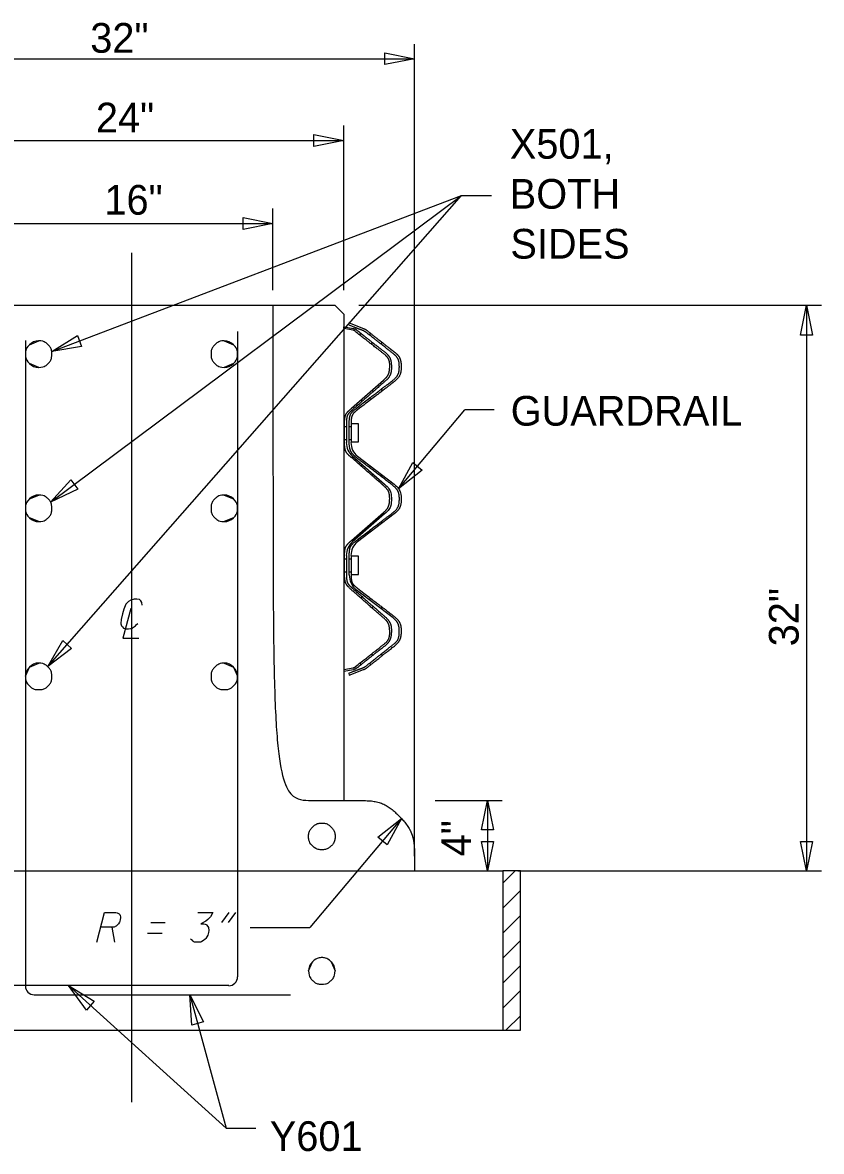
# Model space of a CAD drawing. Extents: x 0 to 680, y 0 to 440.
# Drawn here: x 76.9 to 152, y 200.4 to 306.5 of the extents above; entities that cross this region are included whole.
import ezdxf

# ---------------------------------------------------------------- set-up
doc = ezdxf.new("R2010")
doc.units = 0
doc.layers.add('Default', color=7, linetype='Continuous')

msp = doc.modelspace()

# ---------------------------------------------------------------- linework, layer by layer
at = {"layer": 'Default'}
for p, q in [((113.77, 228.1), (113.77, 304.44)), ((60.56, 303.06), (113.77, 303.06)), ((107.12, 281.31), (107.12, 296.77)), ((79.3, 245.92), (118.2, 290.2)), ((79.54, 261.38), (118.2, 290.2)), ((79.68, 275.54), (118.2, 290.2)), ((118.2, 290.2), (121, 290.2)), ((100.47, 281.31), (100.47, 288.98)), ((87.16, 284.82), (87.16, 204.99)), ((108.53, 279.89), (152.03, 279.89)), ((150.62, 279.89), (150.62, 226.72)), ((107.59, 278.04), (107.64, 278.23)), ((107.64, 278.23), (108.97, 277.7)), ((97.14, 277.43), (97.14, 216.77)), ((107.14, 277.87), (108.03, 277.7)), ((107.14, 277.7), (107.14, 277.87)), ((108, 277.54), (107.14, 277.7)), ((108.64, 277.09), (108.72, 277.23)), ((109.55, 277.09), (109.64, 277.23)), ((77.19, 276.57), (77.19, 215.91)), ((77.58, 276.18), (78.44, 276.54)), ((95.89, 276.54), (96.75, 276.18)), ((109.72, 276.23), (109.83, 276.4)), ((110.64, 276.23), (110.72, 276.4)), ((78.44, 274.05), (77.58, 274.41)), ((96.75, 274.41), (95.89, 274.05)), ((107.86, 270.22), (110.86, 272.85)), ((109.8, 271.91), (109.89, 271.75)), ((110.64, 272), (110.75, 271.83)), ((108.75, 270.97), (108.83, 270.83)), ((109.55, 271.16), (109.64, 271)), ((112.27, 262.63), (118.5, 270.06)), ((121.28, 270.06), (118.5, 270.06)), ((107.2, 266.98), (107.2, 268.81)), ((107.2, 268.5), (107.37, 268.5)), ((107.37, 268.81), (107.37, 266.98)), ((107.64, 266.98), (107.64, 268.81)), ((107.64, 268.5), (107.81, 268.5)), ((107.81, 268.81), (107.81, 266.98)), ((107.2, 267.28), (107.37, 267.28)), ((107.64, 267.28), (107.81, 267.28)), ((107.92, 265.73), (110.94, 263.07)), ((108.42, 265.7), (111.85, 263.07)), ((108.75, 264.79), (108.83, 264.93)), ((109.55, 264.62), (109.64, 264.76)), ((109.8, 263.88), (109.89, 264.01)), ((110.64, 263.77), (110.75, 263.93)), ((77.58, 261.69), (78.44, 262.05)), ((95.89, 262.05), (96.75, 261.69)), ((107.86, 257.78), (110.86, 260.41)), ((110.94, 260.27), (107.95, 257.64)), ((111.85, 260.27), (108.42, 257.64)), ((78.44, 259.55), (77.58, 259.91)), ((96.75, 259.91), (95.89, 259.55)), ((109.8, 259.47), (109.89, 259.33)), ((110.64, 259.58), (110.75, 259.41)), ((108.75, 258.56), (108.83, 258.39)), ((109.55, 258.72), (109.64, 258.58)), ((107.2, 256.06), (107.37, 256.06)), ((107.37, 256.37), (107.37, 254.54)), ((107.64, 254.54), (107.64, 256.37)), ((107.64, 256.06), (107.81, 256.06)), ((107.81, 256.37), (107.81, 254.54)), ((107.2, 254.84), (107.37, 254.84)), ((107.64, 254.84), (107.81, 254.84)), ((111.77, 250.52), (108.31, 253.12)), ((108.75, 252.38), (108.83, 252.52)), ((109.55, 252.18), (109.64, 252.35)), ((109.8, 251.43), (109.89, 251.6)), ((110.64, 251.35), (110.75, 251.52)), ((77.58, 245.86), (78.44, 246.25)), ((95.89, 246.25), (96.75, 245.86)), ((108.64, 246.25), (108.72, 246.11)), ((109.55, 246.25), (109.64, 246.11)), ((109.72, 247.11), (109.83, 246.97)), ((110.64, 247.11), (110.72, 246.97)), ((77.19, 245.01), (77.58, 245.86)), ((96.75, 245.86), (97.14, 245.01)), ((107.14, 245.64), (108, 245.81)), ((107.59, 245.31), (107.64, 245.12)), ((107.64, 245.12), (108.97, 245.64)), ((115.71, 233.34), (122.02, 233.34)), ((120.64, 233.34), (120.64, 226.72)), ((112.55, 231.65), (103.93, 221.4)), ((115.18, 226.72), (122.02, 226.72)), ((123.2, 226.7), (122.08, 225.56)), ((123.49, 226.72), (152.03, 226.72)), ((123.74, 224.89), (122.08, 223.23)), ((96.31, 222.81), (95.62, 221.87)), ((96.95, 222.81), (96.25, 221.87)), ((88.97, 221.87), (90.32, 221.87)), ((123.74, 222.53), (122.08, 220.87)), ((85.31, 221.42), (85.56, 220.01)), ((88.66, 220.87), (90.05, 220.87)), ((98.33, 221.4), (103.93, 221.4)), ((123.74, 220.18), (122.08, 218.52)), ((103.82, 217.32), (104.18, 218.18)), ((105.95, 218.18), (106.31, 217.32)), ((123.74, 217.82), (122.08, 216.16)), ((96.31, 215.94), (72.2, 215.94)), ((81.24, 215.94), (96.06, 202.53)), ((123.74, 215.47), (122.08, 213.81)), ((78.02, 215.08), (102.13, 215.08)), ((92.65, 215.08), (96.06, 202.53)), ((122.36, 211.75), (123.74, 213.11)), ((52.28, 211.75), (122.08, 211.75)), ((96.06, 202.53), (98.86, 202.53))]:
    msp.add_line(p, q, dxfattribs=at)
for points in [[(110.97, 303.61), (113.77, 303.06), (110.97, 302.5)], [(104.32, 295.94), (107.12, 295.38), (104.32, 294.8)], [(97.67, 288.12), (100.47, 287.57), (97.67, 287.01)], [(150.07, 277.09), (150.62, 279.89), (151.2, 277.09)], [(82.48, 276.01), (79.68, 275.54), (82.09, 277.04)], [(114.49, 264.4), (112.27, 262.63), (113.63, 265.12)], [(82.12, 262.6), (79.54, 261.38), (81.46, 263.49)], [(81.54, 247.64), (79.3, 245.92), (80.71, 248.39)], [(120.08, 230.57), (120.64, 233.34), (121.19, 230.57)], [(110.33, 229.88), (112.55, 231.65), (111.19, 229.16)], [(121.19, 229.49), (120.64, 226.72), (120.08, 229.49)], [(151.2, 229.49), (150.62, 226.72), (150.07, 229.49)], [(123.74, 211.75), (123.74, 226.72), (122.08, 226.72), (122.08, 211.75)], [(82.93, 213.64), (81.24, 215.94), (83.67, 214.47)], [(92.85, 212.23), (92.65, 215.08), (93.93, 212.53)]]:
    msp.add_lwpolyline(points, close=True, dxfattribs=at)
for points in [[(60.56, 295.38), (67.21, 295.38), (107.12, 295.38)], [(67.21, 287.57), (73.86, 287.57), (100.47, 287.57)], [(67.21, 233.34), (67.21, 279.06), (68.05, 279.89), (106.28, 279.89), (107.12, 279.06), (107.12, 233.34)], [(107.81, 267.04), (108.5, 267.04), (108.5, 268.75), (107.81, 268.75)], [(107.81, 254.57), (108.5, 254.57), (108.5, 256.31), (107.81, 256.31)], [(88.16, 251.71), (88.13, 251.96), (88.05, 252.1), (87.97, 252.18), (87.91, 252.24), (87.66, 252.27), (87.41, 252.27), (87.11, 252.18), (86.89, 252.04), (86.64, 251.79), (86.44, 251.32), (86.31, 250.88), (86.2, 250.35), (86.17, 249.99), (86.17, 249.94), (86.22, 249.77), (86.25, 249.72), (86.31, 249.66), (86.42, 249.55), (86.53, 249.52), (86.67, 249.47), (86.89, 249.47), (87.08, 249.49), (87.16, 249.52), (87.25, 249.55), (87.36, 249.63), (87.53, 249.77), (87.64, 249.88), (87.75, 249.99)], [(87.11, 251.38), (86.36, 248.61), (87.86, 248.61)], [(107.14, 245.64), (107.14, 245.48), (108.03, 245.64)], [(62.23, 226.72), (112.1, 226.72), (122.08, 226.72), (122.08, 211.75)], [(83.9, 220.01), (84.64, 222.81), (85.7, 222.81), (85.81, 222.78), (85.95, 222.73), (86, 222.7), (86.06, 222.64), (86.11, 222.53), (86.14, 222.42), (86.14, 222.31), (86.11, 222.15), (86.08, 221.98), (86.03, 221.9), (85.95, 221.76), (85.83, 221.62), (85.72, 221.54), (85.64, 221.51), (85.59, 221.48), (85.53, 221.45), (85.31, 221.42), (84.28, 221.42)], [(93.4, 222.81), (94.81, 222.81), (94.59, 222.42), (94.34, 222.15), (94.15, 222.01), (93.68, 221.76), (93.98, 221.76), (94.09, 221.73), (94.18, 221.67), (94.23, 221.65), (94.34, 221.51), (94.42, 221.4), (94.45, 221.12), (94.42, 220.93), (94.34, 220.68), (94.15, 220.37), (94.09, 220.32), (93.93, 220.18), (93.79, 220.09), (93.68, 220.04), (93.51, 220.01), (93.26, 220.01), (93.09, 220.04), (92.98, 220.09), (92.93, 220.15), (92.82, 220.23), (92.73, 220.34)]]:
    msp.add_lwpolyline(points, dxfattribs=at)
for centre, radius, start, end in [((78.44, 275.32), 1.22, 90.2249, 135.277), ((95.89, 275.32), 1.22, 44.723, 89.7751), ((78.44, 275.26), 1.22, 224.723, 269.7751), ((95.89, 275.26), 1.22, 270.2249, 315.277), ((109.04, 266.98), 1.68, 179.8804, 229.1953), ((109.42, 266.97), 1.62, 179.6332, 231.4869), ((78.44, 260.83), 1.22, 90.2249, 135.277), ((95.89, 260.83), 1.22, 44.723, 89.7751), ((78.44, 260.77), 1.22, 224.723, 269.7751), ((95.89, 260.77), 1.22, 270.2249, 315.277), ((109.04, 256.37), 1.68, 130.805, 180.12), ((109.42, 256.38), 1.62, 128.5133, 180.367), ((109.46, 254.53), 1.82, 179.7369, 230.6652), ((78.43, 245.12), 1.14, 89.8007, 138.8084), ((95.9, 245.12), 1.14, 41.1916, 90.1993), ((78.33, 245.01), 1.14, 131.1916, 180.1993), ((96, 245.01), 1.14, 359.8007, 48.8084), ((105.03, 217.32), 1.22, 134.723, 179.7751), ((105.1, 217.32), 1.22, 0.2249, 45.277), ((96.32, 216.75), 0.816, 268.9487, 1.0507), ((78.02, 215.91), 0.834, 180.162, 269.8374)]:
    msp.add_arc(centre, radius, start, end, dxfattribs=at)
for points, degree in [([(100.47, 279.89), (100.47, 264.37), (100.47, 248.86), (100.47, 233.34), (103.24, 233.34), (106.01, 233.34), (108.78, 233.34), (110.11, 233.34), (111.38, 232.84), (112.3, 231.9), (113.25, 230.95), (113.77, 229.7), (113.77, 228.35), (113.77, 227.81), (113.77, 227.26), (113.77, 226.72)], 4), ([(107.59, 278.04), (108.03, 277.87), (108.47, 277.7), (108.92, 277.54), (109, 277.51), (109.06, 277.45), (109.14, 277.43)], 4), ([(108.34, 277.56), (109.21, 276.87), (110.09, 276.18), (110.97, 275.49), (111.38, 275.18), (111.6, 274.66), (111.6, 274.1), (111.61, 273.54), (111.37, 273.04), (110.94, 272.69), (109.94, 271.81), (108.94, 270.93), (107.95, 270.06)], 4), ([(108.22, 277.43), (108.17, 277.48), (108.09, 277.51), (108, 277.54)], 2), ([(108.03, 277.7), (108.14, 277.68), (108.25, 277.65), (108.34, 277.56)], 2), ([(110.86, 272.85), (111.22, 273.13), (111.44, 273.6), (111.44, 274.1), (111.47, 274.6), (111.24, 275.04), (110.86, 275.35), (109.98, 276.03), (109.1, 276.72), (108.22, 277.4)], 4), ([(108.31, 270.22), (109.46, 271.1), (110.62, 271.98), (111.77, 272.85), (112.13, 273.13), (112.35, 273.6), (112.35, 274.1), (112.35, 274.6), (112.16, 275.04), (111.77, 275.35), (110.89, 276.03), (110.02, 276.72), (109.14, 277.4)], 4), ([(108.97, 277.7), (109.06, 277.68), (109.17, 277.62), (109.25, 277.56), (110.13, 276.87), (111, 276.18), (111.88, 275.49), (112.3, 275.18), (112.52, 274.66), (112.52, 274.1), (112.52, 273.54), (112.28, 273.04), (111.85, 272.69), (110.71, 271.81), (109.56, 270.93), (108.42, 270.06)], 4), ([(77.58, 276.18), (77.33, 275.93), (77.19, 275.63), (77.19, 275.29), (77.19, 274.96), (77.33, 274.66), (77.58, 274.41)], 3), ([(78.44, 274.05), (78.77, 274.05), (79.1, 274.18), (79.32, 274.41), (79.57, 274.66), (79.68, 274.96), (79.68, 275.29), (79.68, 275.63), (79.57, 275.93), (79.32, 276.18), (79.1, 276.4), (78.77, 276.54), (78.44, 276.54)], 3), ([(95.89, 276.54), (95.56, 276.54), (95.23, 276.4), (95.01, 276.18), (94.76, 275.93), (94.65, 275.63), (94.65, 275.29), (94.65, 274.96), (94.76, 274.66), (95.01, 274.41), (95.23, 274.18), (95.56, 274.05), (95.89, 274.05)], 3), ([(96.75, 274.41), (97, 274.66), (97.14, 274.96), (97.14, 275.29), (97.14, 275.63), (97, 275.93), (96.75, 276.18)], 3), ([(107.2, 268.81), (107.2, 269.36), (107.45, 269.89), (107.86, 270.19)], 2), ([(107.95, 270.06), (107.59, 269.78), (107.37, 269.31), (107.37, 268.81)], 2), ([(107.64, 268.81), (107.64, 269.36), (107.89, 269.89), (108.31, 270.19)], 2), ([(108.42, 270.06), (108.03, 269.78), (107.81, 269.31), (107.81, 268.81)], 2), ([(107.86, 265.57), (107.45, 265.87), (107.2, 266.4), (107.2, 266.98)], 2), ([(108.31, 257.78), (109.46, 258.66), (110.62, 259.53), (111.77, 260.41), (112.13, 260.69), (112.35, 261.16), (112.35, 261.66), (112.36, 262.16), (112.15, 262.61), (111.77, 262.93), (110.62, 263.81), (109.46, 264.69), (108.31, 265.57), (107.89, 265.87), (107.64, 266.4), (107.64, 266.98)], 4), ([(110.86, 260.41), (111.22, 260.69), (111.44, 261.16), (111.44, 261.66), (111.45, 262.16), (111.24, 262.61), (110.86, 262.93), (109.86, 263.81), (108.86, 264.69), (107.86, 265.57)], 4), ([(110.94, 263.07), (111.36, 262.77), (111.6, 262.24), (111.6, 261.66), (111.6, 261.11), (111.36, 260.58), (110.94, 260.27)], 3), ([(111.85, 263.07), (112.27, 262.77), (112.52, 262.24), (112.52, 261.66), (112.52, 261.11), (112.27, 260.58), (111.85, 260.27)], 3), ([(77.58, 261.69), (77.33, 261.44), (77.19, 261.13), (77.19, 260.8), (77.19, 260.47), (77.33, 260.14), (77.58, 259.91)], 3), ([(78.44, 259.55), (78.77, 259.55), (79.1, 259.69), (79.32, 259.91), (79.57, 260.14), (79.68, 260.47), (79.68, 260.8), (79.68, 261.13), (79.57, 261.44), (79.32, 261.69), (79.1, 261.91), (78.77, 262.05), (78.44, 262.05)], 3), ([(95.89, 262.05), (95.56, 262.05), (95.23, 261.91), (95.01, 261.69), (94.76, 261.44), (94.65, 261.13), (94.65, 260.8), (94.65, 260.47), (94.76, 260.14), (95.01, 259.91), (95.23, 259.69), (95.56, 259.55), (95.89, 259.55)], 3), ([(96.75, 259.91), (97, 260.14), (97.14, 260.47), (97.14, 260.8), (97.14, 261.13), (97, 261.44), (96.75, 261.69)], 3), ([(107.2, 256.37), (107.2, 256.95), (107.45, 257.45), (107.86, 257.78)], 2), ([(107.64, 256.37), (107.64, 256.95), (107.89, 257.45), (108.31, 257.78)], 2), ([(108.22, 245.92), (109.1, 246.61), (109.98, 247.31), (110.86, 248), (111.24, 248.28), (111.47, 248.75), (111.44, 249.25), (111.44, 249.74), (111.22, 250.22), (110.86, 250.49), (109.86, 251.37), (108.86, 252.25), (107.86, 253.12), (107.43, 253.48), (107.2, 253.98), (107.2, 254.54), (107.2, 255.15), (107.2, 255.76), (107.2, 256.37)], 4), ([(107.37, 254.54), (107.37, 254.04), (107.59, 253.57), (107.95, 253.29)], 2), ([(107.81, 254.54), (107.81, 254.04), (108.03, 253.57), (108.42, 253.29)], 2), ([(107.95, 253.29), (108.94, 252.41), (109.94, 251.54), (110.94, 250.66), (111.37, 250.31), (111.61, 249.8), (111.6, 249.25), (111.6, 248.69), (111.38, 248.16), (110.97, 247.86)], 4), ([(108.42, 253.29), (109.56, 252.41), (110.71, 251.54), (111.85, 250.66), (112.28, 250.31), (112.52, 249.8), (112.52, 249.25), (112.52, 248.69), (112.3, 248.16), (111.88, 247.86)], 4), ([(109.14, 245.92), (110.02, 246.61), (110.89, 247.31), (111.77, 248), (112.16, 248.28), (112.35, 248.75), (112.35, 249.25), (112.35, 249.74), (112.13, 250.22), (111.77, 250.49)], 4), ([(110.97, 247.86), (110.09, 247.17), (109.21, 246.47), (108.34, 245.78), (108.25, 245.7), (108.14, 245.67), (108.03, 245.64)], 4), ([(108.97, 245.64), (109.06, 245.67), (109.17, 245.73), (109.25, 245.78), (110.13, 246.47), (111, 247.17), (111.88, 247.86)], 4), ([(77.19, 245.01), (77.19, 244.67), (77.33, 244.34), (77.58, 244.12), (77.8, 243.87), (78.1, 243.76), (78.44, 243.76), (78.77, 243.76), (79.1, 243.87), (79.32, 244.12), (79.57, 244.34), (79.68, 244.67), (79.68, 245.01), (79.68, 245.34), (79.57, 245.64), (79.32, 245.86), (79.1, 246.11), (78.77, 246.25), (78.44, 246.25)], 3), ([(95.89, 246.25), (95.56, 246.25), (95.23, 246.11), (95.01, 245.86), (94.76, 245.64), (94.65, 245.34), (94.65, 245.01), (94.65, 244.67), (94.76, 244.34), (95.01, 244.12), (95.23, 243.87), (95.56, 243.76), (95.89, 243.76), (96.23, 243.76), (96.53, 243.87), (96.75, 244.12), (97, 244.34), (97.14, 244.67), (97.14, 245.01)], 3), ([(107.59, 245.31), (108.03, 245.48), (108.47, 245.64), (108.92, 245.81), (109, 245.84), (109.06, 245.89), (109.14, 245.92)], 4), ([(108, 245.81), (108.09, 245.84), (108.17, 245.86), (108.22, 245.92)], 2), ([(104.18, 229.07), (104.43, 228.85), (104.73, 228.71), (105.07, 228.71), (105.4, 228.71), (105.7, 228.85), (105.95, 229.07), (106.17, 229.29), (106.31, 229.63), (106.31, 229.96), (106.31, 230.29), (106.17, 230.6), (105.95, 230.85), (105.7, 231.07), (105.4, 231.21), (105.07, 231.21), (104.73, 231.21), (104.43, 231.07), (104.18, 230.85), (103.96, 230.6), (103.82, 230.29), (103.82, 229.96), (103.82, 229.63), (103.96, 229.29), (104.18, 229.07)], 3), ([(105.95, 218.18), (105.7, 218.43), (105.4, 218.57), (105.07, 218.57), (104.73, 218.57), (104.43, 218.43), (104.18, 218.18)], 3), ([(103.82, 217.32), (103.82, 216.99), (103.96, 216.66), (104.18, 216.44), (104.43, 216.19), (104.73, 216.08), (105.07, 216.08), (105.4, 216.08), (105.7, 216.19), (105.95, 216.44), (106.17, 216.66), (106.31, 216.99), (106.31, 217.32)], 3)]:
    msp.add_open_spline(points, degree=degree, dxfattribs=at)

# ---------------------------------------------------------------- texts
for s, p in [('32"', (83.29, 303.62)), ('24"', (83.82, 296.13)), ('X501,', (122.74, 293.66)), ('BOTH', (122.73, 288.96)), ('16"', (84.62, 288.4)), ('SIDES', (122.79, 284.27)), ('GUARDRAIL', (122.82, 268.57)), ('Y601', (100.17, 200.4))]:
    msp.add_text(s, height=2.793, dxfattribs=at).set_placement(p)
for s, p in [('32"', (149.89, 247.83)), ('4"', (119.08, 228.09))]:
    msp.add_text(s, height=2.793, rotation=90, dxfattribs=at).set_placement(p)

doc.saveas('drawing.dxf')
